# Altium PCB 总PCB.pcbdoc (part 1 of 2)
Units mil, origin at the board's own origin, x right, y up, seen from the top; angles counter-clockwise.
Board outline 1771.65 x 3543.31 mil, 2 copper layers (Top Layer, Bottom Layer), stack 62.205 mil thick; 115 components, 80 nets, 419 pads, 214 vias.
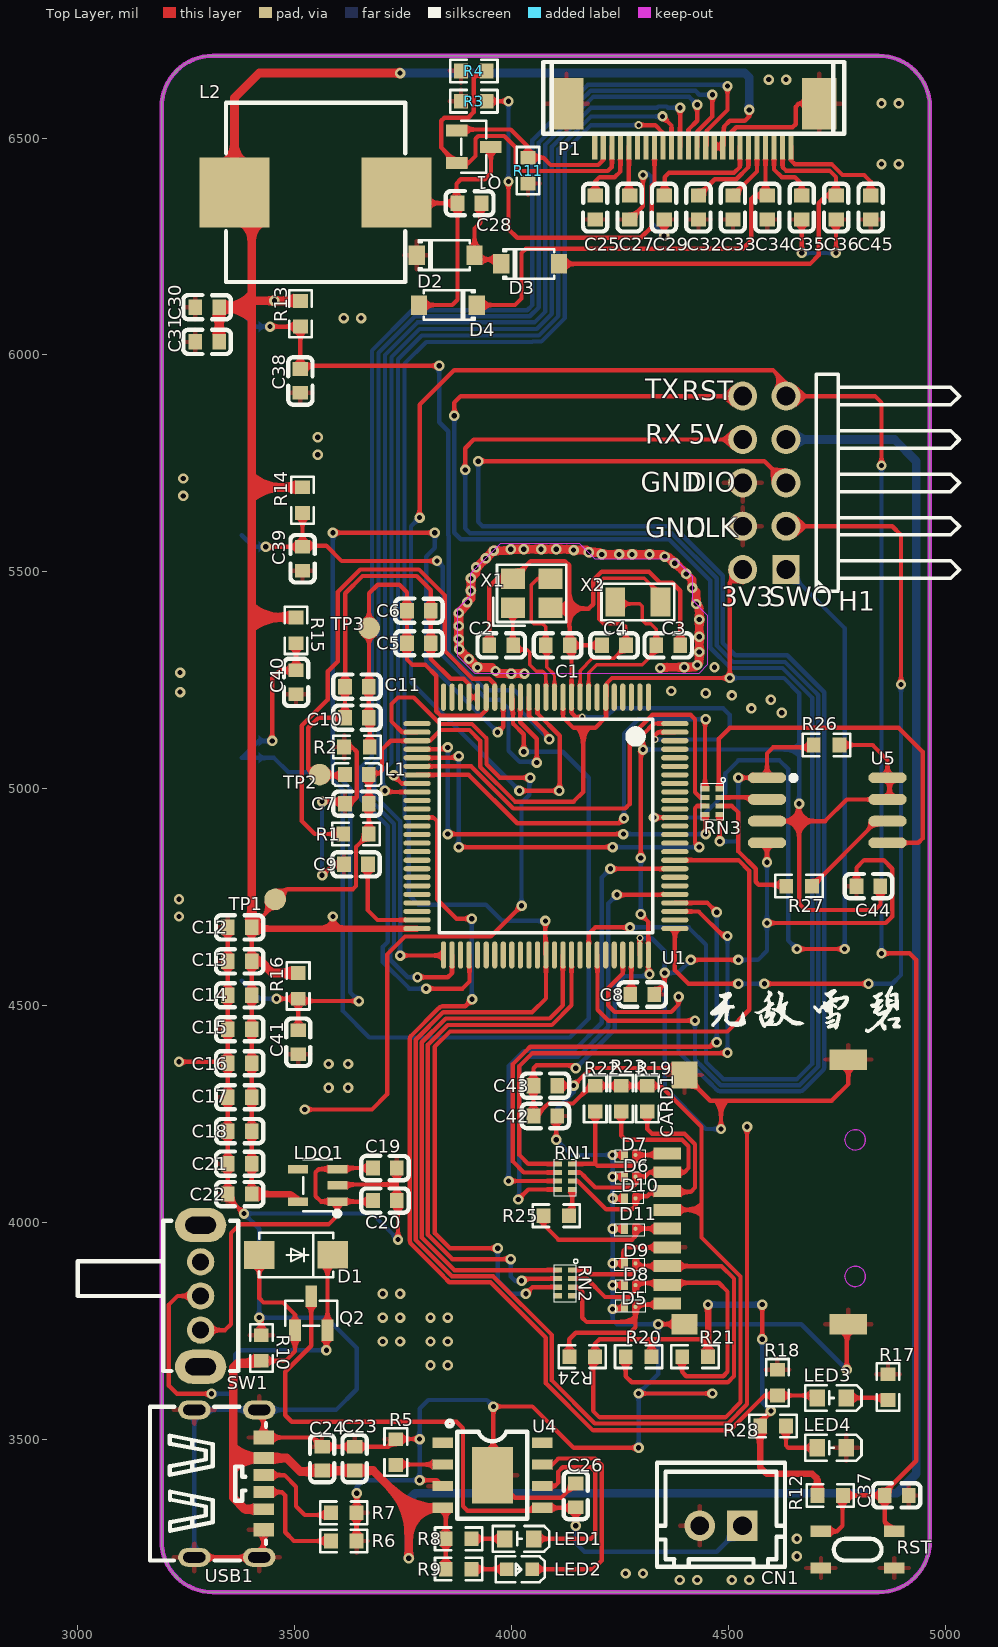
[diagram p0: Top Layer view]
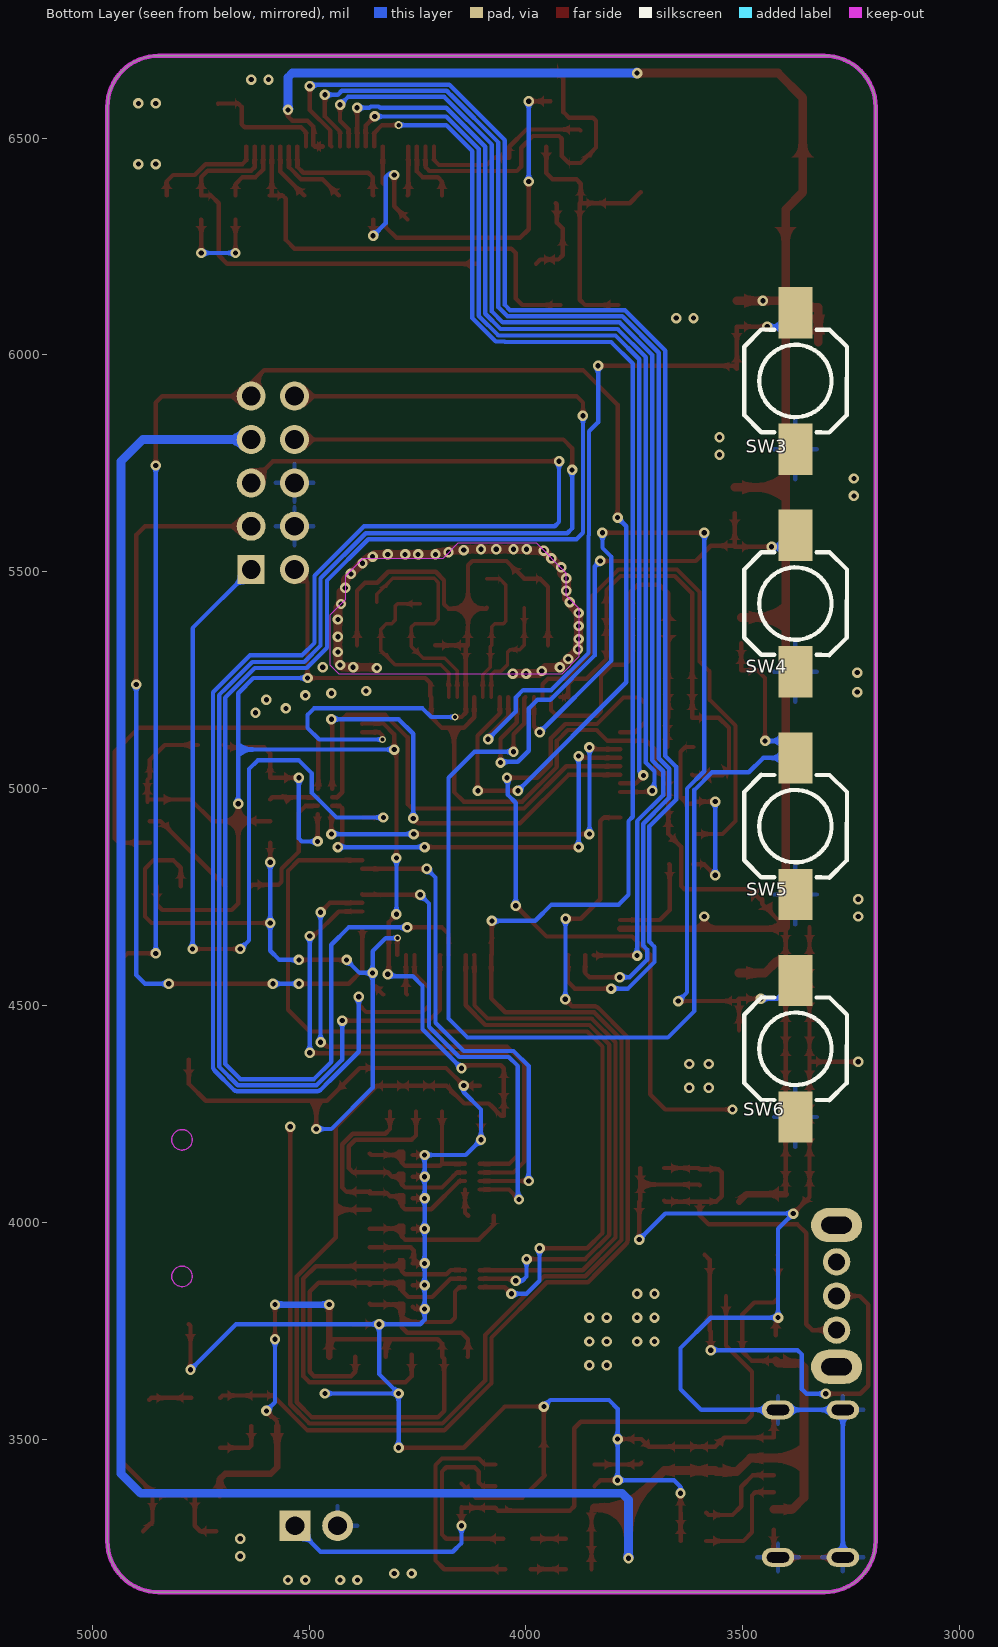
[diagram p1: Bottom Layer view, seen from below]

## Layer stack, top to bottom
Top Solder Mask Layer: solder mask 0.394, Dk 3.3
Top Layer: signal copper 1.378
Dielectric1: surface 59.449, FR4, Dk 4.5
Bottom Layer: signal copper 1.378
Bottom Solder Mask Layer: solder mask 0.394, Dk 3.3

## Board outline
3311.58,6690 4847.01,6690 cw(c4847.01,6571.89) 4965.12,6571.89 4965.12,3264.8 cw(c4847.01,3264.8) 4847.01,3146.69 3311.58,3146.69 cw(c3311.58,3264.8) 3193.47,3264.8 3193.47,6571.89 cw(c3311.58,6571.89)

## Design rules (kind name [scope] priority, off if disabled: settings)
BoardOutlineClearance copperThickness1oz [All] p0: genericclearance=10 ignorepadtopadclearanceinfootprint=FALSE except(0: Arc-SplitContinuation Track-SplitContinuation SMDPad-SplitContinuation THPad-SplitContinuation Via-SplitContinuation Fill-SplitContinuation Poly-SplitContinuation Region-SplitContinuation Text-SplitContinuation)
BoardOutlineClearance copperThickness2oz [All] p0: genericclearance=10 ignorepadtopadclearanceinfootprint=FALSE except(0: Arc-SplitContinuation Track-SplitContinuation SMDPad-SplitContinuation THPad-SplitContinuation Via-SplitContinuation Fill-SplitContinuation Poly-SplitContinuation Region-SplitContinuation Text-SplitContinuation)
BoardOutlineClearance copperThicknessInner0.5oz [All] p0: genericclearance=10 ignorepadtopadclearanceinfootprint=FALSE except(0: Arc-SplitContinuation Track-SplitContinuation SMDPad-SplitContinuation THPad-SplitContinuation Via-SplitContinuation Fill-SplitContinuation Poly-SplitContinuation Region-SplitContinuation Text-SplitContinuation)
BoardOutlineClearance otherClearance [All] p0: genericclearance=10 ignorepadtopadclearanceinfootprint=FALSE except(0: Arc-SplitContinuation Track-SplitContinuation SMDPad-SplitContinuation THPad-SplitContinuation Via-SplitContinuation Fill-SplitContinuation Poly-SplitContinuation Region-SplitContinuation Text-SplitContinuation)
Clearance copperThickness1oz [All] p1: gap=7 ignorepadtopadclearanceinfootprint=FALSE
Clearance copperThickness2oz [All] p1: gap=7 ignorepadtopadclearanceinfootprint=FALSE
Clearance copperThicknessInner0.5oz [All] p1: gap=7 ignorepadtopadclearanceinfootprint=FALSE
Clearance otherClearance [All] p1: gap=7 ignorepadtopadclearanceinfootprint=FALSE
DiffPairsRouting differentialPair [All] p1: maxuncoupledlength=10 minlimit=5.9843 maxlimit=Infinity mostfreqgap=5.9843 toplayer_minwidth=5 toplayer_prefwidth=10 toplayer_maxwidth=100 bottomlayer_minwidth=5 bottomlayer_prefwidth=10 bottomlayer_maxwidth=100
PasteMaskExpansion pasteMaskExpansion [All] p1: expansion=0
PlaneConnect innerPlane [All] p1: planeconnectstyle=Relief reliefexpansion=20 reliefentries=4 reliefconductorwidth=10 reliefairgap=10
PolygonConnect copperRegion [All] p1: connectstyle=Relief reliefentries=4 reliefconductorwidth=10 polygonreliefangle="90 Angle" airgapwidth=10
RoutingVias viaSize [All] p1: viastyle="Through Hole" holewidth=12.0078 minholewidth=7.874 maxholewidth=248.0314 width=12.0078 minwidth=7.874 maxwidth=248.0314
SolderMaskExpansion solderMaskExpansion [IsVia] p1: useseparateexpansions=TRUE expansion=-1000 expansionbottom=-1000
SolderMaskExpansion solderMaskExpansion [All] p2: useseparateexpansions=TRUE expansion=2.0079 expansionbottom=2.0079
Width copperThickness1oz [All] p1: maxlimit=100 minlimit=4 preferedwidth=10
Width copperThickness2oz [All] p1: maxlimit=100 minlimit=8 preferedwidth=10
Width copperThickness0.5oz [All] p1: maxlimit=100 minlimit=4 preferedwidth=10

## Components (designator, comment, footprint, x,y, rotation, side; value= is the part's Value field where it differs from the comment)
C1 "20pF" C0603#1 4106.72,5330.21 r180 top
C2 "20pF" C0603#1 3976.72,5330.21 r0 top
C3 "12pF" C0603#1 4361.72,5330.21 r180 top
C4 "12pF" C0603#1 4236.72,5330.21 r0 top
C5 "1uF" C0603#1 3786.72,5335.21 r0 top
C6 "100nF" C0603#1 3786.72,5410.21 r180 top
C7 "100nF" C0603#1 3643.91,4965.21 r180 top
C8 "2.2uF" C0603#1 4301.72,4525.21 r180 top
C9 "2.2uF" C0603#1 3641.72,4825.21 r0 top
C10 "1uF" C0603#1 3643.91,5163.57 r0 top
C11 "100nF" C0603#1 3643.91,5235.21 r180 top
C12 "10uF" C0603#1 3373.47,4680 r0 top
C13 "100nF" C0603#1 3373.47,4601.67 r0 top
C14 "100nF" C0603#1 3373.47,4523.33 r0 top
C15 "100nF" C0603#1 3373.47,4445 r0 top
C16 "100nF" C0603#1 3373.47,4366.67 r0 top
C17 "100nF" C0603#1 3373.47,4288.33 r0 top
C18 "100nF" C0603#1 3373.47,4210 r0 top
C19 "100nF" C0603#1 3708.47,4125 r180 top
C20 "1uF" C0603#1 3708.47,4050 r180 top
C21 "1uF" C0603#1 3373.47,4135 r0 top
C22 "100nF" C0603#1 3373.47,4065 r0 top
C23 "22uF" C0603#1 3638.47,3455 r270 top
C24 "100nF" C0603#1 3563.47,3455 r90 top
C25 "100nF" C0603#2 4193.47,6340 r90 top
C26 "10uF" C0603#1 4148.47,3370 r270 top
C27 "100nF" C0603#2 4272.84,6340 r90 top
C28 "100nF" C0603#2 3903.47,6350 r180 top
C29 "100nF" C0603#2 4352.22,6340 r90 top
C30 "100nF" C0603#2 3298.47,6110 r0 top
C31 "100nF" C0603#2 3298.47,6030 r0 top
C32 "100nF" C0603#2 4431.59,6340 r90 top
C33 "100nF" C0603#2 4510.97,6340 r90 top
C34 "100nF" C0603#2 4590.34,6340 r90 top
C35 "100nF" C0603#2 4669.72,6340 r90 top
C36 "100nF" C0603#2 4749.09,6340 r90 top
C37 "100nF" C0603#1 4888.47,3370 r0 top
C38 "100nF" C0603#1 3513.47,5940 r90 top
C39 "100nF" C0603#1 3518.47,5530 r90 top
C40 "100nF" C0603#1 3503.47,5245 r90 top
C41 "100nF" C0603#1 3508.47,4415 r90 top
C42 "10uF" C0603#1 4078.47,4245 r0 top
C43 "100nF" C0603#1 4078.47,4315 r180 top
C44 "100nF" C0603#1 4823.47,4775 r180 top
C45 "100nF" C0603#2 4828.47,6340 r90 top
CARD1 "XKTF-015-G" TF-SMD_XKTF-015-N 4568.47,4070 r90 top
CN1 "ZX-XH2.54-2PZZ" CONN-TH_2P-P2.50_HX25003-2A 4483.47,3300 r180 top
D1 "SS34" SMA_L4.3-W2.6-LS5.0-FD 3503.47,3925 r0 top
D2 "B5819W" SOD-123_L2.8-W1.8-LS3.7-RD 3848.47,6230 r0 top
D3 "B5819W" SOD-123_L2.8-W1.8-LS3.7-RD 4043.47,6210 r0 top
D4 "B5819W" SOD-123_L2.8-W1.8-LS3.7-RD 3853.47,6115 r180 top
D5 "LESD8D5.0CAT5G" DFN-2L_L1.0-W0.6-P0.65-BI 4273.47,3805 r180 top
D6 "LESD8D5.0CAT5G" DFN-2L_L1.0-W0.6-P0.65-BI 4273.47,4105 r180 top
D7 "LESD8D5.0CAT5G" DFN-2L_L1.0-W0.6-P0.65-BI 4273.47,4155 r180 top
D8 "LESD8D5.0CAT5G" DFN-2L_L1.0-W0.6-P0.65-BI 4273.47,3855 r180 top
D9 "LESD8D5.0CAT5G" DFN-2L_L1.0-W0.6-P0.65-BI 4273.47,3905 r180 top
D10 "LESD8D5.0CAT5G" DFN-2L_L1.0-W0.6-P0.65-BI 4273.47,4055 r180 top
D11 "LESD8D5.0CAT5G" DFN-2L_L1.0-W0.6-P0.65-BI 4273.47,3985 r180 top
H1 "PH2.54-07-05PWS" HDR-TH_10P-P2.54-H-M-R2-C5-S2.54-W12.9 4583.47,5705 r90 top
L1 "GZ1608D601TF" L0603 3643.91,5032.49 r180 top
L2 "68uH" IND-SMD_L11.5-W10.5_SRG1040 3548.47,6375 r0 top
LDO1 "ME6211C33M5G-N" SOT-23-5_L3.0-W1.7-P0.95-LS2.8-BL 3553.47,4085 r90 top
LED1 "GL0603UR01" LED0603-FD 4018.47,3270 r0 top
LED2 "MHT192DUGCT" LED0603-RD 4018.47,3200 r180 top
LED3 "GL0603UR01" LED0603-FD 4738.47,3595 r0 top
LED4 "GL0603UR01" LED0603-FD 4738.47,3480 r0 top
P1 "AFC07-S24ECC-00" FPC-SMD_24P-L17.5-W5.4-P0.50 4418.47,6530 r180 top
Q1 "SI2300" SOT-23-3_L2.9-W1.3-P1.90-LS2.4-BR#1 3913.47,6480 r180 top
Q2 "DMP1045U-7" SOT-23-3_L2.9-W1.3-P1.90-LS2.4-BR#2 3538.47,3790 r270 top
R1 "0Ω" R0603 3641.72,4895.21 r180 top
R2 "0Ω" R0603 3643.91,5095.87 r0 top
R3 "10K" R0603 3913.47,6585 r0 top
R4 "10K" R0603 3913.47,6655 r180 top
R5 "1.2kΩ" R0603 3733.47,3470 r270 top
R6 "5.1kΩ" R0603 3613.47,3265 r0 top
R7 "5.1kΩ" R0603 3613.47,3330 r0 top
R8 "1kΩ" R0603 3878.47,3270 r0 top
R9 "1kΩ" R0603 3878.47,3200 r0 top
R10 "10kΩ" R0603 3423.47,3710 r90 top
R11 "10K" R0603 4038.47,6425 r90 top
R12 "10kΩ" R0603 4735.36,3370.1 r180 top
R13 "10K" R0603 3513.47,6095 r90 top
R14 "10K" R0603 3518.47,5665 r90 top
R15 "10K" R0603 3503.47,5365 r90 top
R16 "10K" R0603 3508.47,4545 r90 top
R17 "2kΩ" R0603 4868.47,3620 r90 top
R18 "10kΩ" R0603 4613.47,3630 r270 top
R19 "47kΩ" R0603 4313.47,4285 r90 top
R20 "47kΩ" R0603 4293.47,3690 r0 top
R21 "47kΩ" R0603 4423.47,3690 r0 top
R22 "47kΩ" R0603 4193.47,4285 r90 top
R23 "47kΩ" R0603 4253.47,4285 r90 top
R24 "47kΩ" R0603 4163.47,3690 r0 top
R25 "22Ω" R0603 4103.47,4015 r180 top
R26 "10kΩ" R0603 4726.89,5100.5 r0 top
R27 "22Ω" R0603 4663.47,4775 r180 top
R28 "2kΩ" R0603 4603.47,3530 r0 top
RN1 "0Ω" RES-ARRAY-SMD_0402-8P-L2.0-W1.0-BL 4123.47,4105 r270 top
RN2 "0Ω" RES-ARRAY-SMD_0402-8P-L2.0-W1.0-BL 4123.47,3860 r270 top
RN3 "0Ω" RES-ARRAY-SMD_0402-8P-L2.0-W1.0-BL 4463.47,4970 r270 top
RST "TSA017A2540A03" SW-SMD_4P-L4.2-W3.4-P2.15-LS5.2 4798.47,3245 r180 top
SW1 "SK12D07VG5" SW-TH_SK12D07VG5-1 3283.47,3830 r270 top
SW3 "TS-1817A-5026" SW-SMD_L6.0-W6.0-LS8.0 3378.47,5940 r90 bottom
SW4 "TS-1817A-5026" SW-SMD_L6.0-W6.0-LS8.0 3378.47,5426.67 r90 bottom
SW5 "TS-1817A-5026" SW-SMD_L6.0-W6.0-LS8.0 3378.47,4913.33 r90 bottom
SW6 "TS-1817A-5026" SW-SMD_L6.0-W6.0-LS8.0 3378.47,4400 r90 bottom
TP1 "" Test-Point-0.5mm 3455.17,4744.65 r0 top
TP2 "" Test-Point-0.5mm 3558.12,5032.28 r0 top
TP3 "" Test-Point-0.5mm 3671.72,5370.21 r0 top
U1 "" LQFP-100_L14.0-W14.0-P0.50-LS16.0-BL 4079.75,4913.56 r180 top locked
U4 "TC4056A." ESOP-8_L4.9-W3.9-P1.27-LS6.0-BL-EP 3956.19,3416.49 r270 top
U5 "GD25Q32CSIGR" SOIC-8_L5.3-W5.3-P1.27-LS8.0-BL 4728.47,4950 r270 top
USB1 "TYPE-C 6P" TYPE-C-SMD_TYPE-C-6P_1 3348.73,3397.2 r270 top
X1 "8MHz" CRYSTAL-SMD_4P-L3.2-W2.5-BL 4046.72,5450.21 r0 top
X2 "32.768kHz" OSC-SMD_2P-L3.2-W1.5 4291.72,5430.21 r0 top

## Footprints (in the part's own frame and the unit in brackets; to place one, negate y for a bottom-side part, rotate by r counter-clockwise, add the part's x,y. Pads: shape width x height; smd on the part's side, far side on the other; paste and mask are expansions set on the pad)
C0603#1 [mm]
  rect 0.8x0.9 smd: 1(-0.7,0) 2(0.7,0)
  silkscreen extent -1.39,-0.71 1.39,0.71
C0603#2 [mm]
  rect 0.8x0.9 smd paste+0 mask+0.051: 1(-0.7,0) 2(0.7,0)
  silkscreen extent -1.41,-0.71 1.39,0.72
CONN-TH_2P-P2.50_HX25003-2A [mm]
  rect 1.8x1.8 hole 1.1 paste+0 mask+0.05: 1(-1.25,0)
  round 1.8 hole 1.1 paste+0 mask+0.05: 2(1.25,0)
  silkscreen extent -3.75,-3.7 3.75,2.41
CRYSTAL-SMD_4P-L3.2-W2.5-BL [mm]
  rect 1.4x1.2 smd: 1(-1.1,-0.85) 2(1.1,-0.85) 3(1.1,0.85) 4(-1.1,0.85)
  silkscreen extent -2.26,-1.91 2.03,1.68
DFN-2L_L1.0-W0.6-P0.65-BI [mm]
  round 0.246 smd: 1(-0.325,0)
  rect 0.4x0.6 smd: 2(0.325,0)
  Top Layer region: -0.53,0.3 -0.53,-0.3 -0.2,-0.3 -0.12,-0.2 -0.12,0.3
ESOP-8_L4.9-W3.9-P1.27-LS6.0-BL-EP [mm]
  rect 0.6x1.2 smd: 1(-1.905,-2.908) 2(-0.635,-2.908) 3(0.635,-2.908) 4(1.905,-2.908) 5(1.905,2.908) 6(0.635,2.908) 7(-0.635,2.908) 8(-1.905,2.908)
  rect 3.3x2.4 smd: 9(0,0)
  silkscreen extent -3.2,-2.67 2.55,2.05
FPC-SMD_24P-L17.5-W5.4-P0.50 [mm]
  rect 0.3x1.5 smd: 1(5.745,1.25) 2(5.245,1.25) 3(4.746,1.25) 4(4.245,1.25) 5(3.746,1.25) 6(3.245,1.25) 7(2.746,1.25) 8(2.245,1.25) 9(1.746,1.25) 10(1.245,1.25) 11(0.746,1.25) 12(0.245,1.25) 13(-0.254,1.25) 14(-0.755,1.25) 15(-1.251,1.25) 16(-1.754,1.25) 17(-2.254,1.25) 18(-2.754,1.25) 19(-3.254,1.25) 20(-3.756,1.25) 21(-4.256,1.25) 22(-4.756,1.25) 23(-5.256,1.25) 24(-5.757,1.25)
  rect 2x3 smd: 25(-7.401,-1.25) 26(7.401,-1.25)
  silkscreen extent -8.87,-3.7 8.77,0.5
HDR-TH_10P-P2.54-H-M-R2-C5-S2.54-W12.9 [mm]
  rect 1.7x1.575 hole 1.1: 1(-5.08,-1.27)
  round 1.7 hole 1.1: 2(-5.08,1.27) 3(-2.54,-1.27) 4(-2.54,1.27) 5(0,-1.27) 6(0,1.27) 7(2.54,-1.27) 8(2.54,1.27) 9(5.08,-1.27) 10(5.08,1.27)
  silkscreen extent -6.35,-11.43 6.35,-3.05
IND-SMD_L11.5-W10.5_SRG1040 [mm]
  rect 4.1x4.1 smd: 1(-4.75,0) 2(4.75,0)
  silkscreen extent -5.25,-5.25 5.25,5.25
L0603 [mm]
  rect 0.8x0.864 smd paste-100 mask+0.051: 1(-0.7,0) 2(0.7,0)
  silkscreen extent -1.42,-0.65 1.42,0.65
LED0603-FD [mm]
  rect 0.9x1 smd: 1(-0.85,0) 2(0.85,0)
  silkscreen extent -1.55,-0.75 1.75,0.75
LED0603-RD [mm]
  rect 0.8x0.8 smd: 1(-0.749,0) 2(0.749,0)
  silkscreen extent -1.49,-0.75 1.39,0.76
LQFP-100_L14.0-W14.0-P0.50-LS16.0-BL [mm]
  oval 0.3x1.6 smd paste-100 mask+0.051: 1(-6,-7.55) 2(-5.5,-7.55) 3(-5,-7.55) 4(-4.5,-7.55) 5(-4,-7.55) 6(-3.5,-7.55) 7(-3,-7.55) 8(-2.5,-7.55) 9(-2,-7.55) 10(-1.5,-7.55) 11(-1,-7.55) 12(-0.5,-7.55) 13(0,-7.55) 14(0.5,-7.55) 15(1,-7.55) 16(1.5,-7.55) 17(2,-7.55) 18(2.5,-7.55) 19(3,-7.55) 20(3.5,-7.55) 21(4,-7.55) 22(4.5,-7.55) 23(5,-7.55) 24(5.5,-7.55) 25(6,-7.55) 51(6,7.55) 52(5.5,7.55) 53(5,7.55) 54(4.5,7.55) 55(4,7.55) 56(3.5,7.55) 57(3,7.55) 58(2.5,7.55) 59(2,7.55) 60(1.5,7.55) 61(1,7.55) 62(0.5,7.55) 63(0,7.55) 64(-0.5,7.55) 65(-1,7.55) 66(-1.5,7.55) 67(-2,7.55) 68(-2.5,7.55) 69(-3,7.55) 70(-3.5,7.55) 71(-4,7.55) 72(-4.5,7.55) 73(-5,7.55) 74(-5.5,7.55) 75(-6,7.55)
  oval 1.6x0.3 smd paste-100 mask+0.051: 26(7.55,-6) 27(7.55,-5.5) 28(7.55,-5) 29(7.55,-4.5) 30(7.55,-4) 31(7.55,-3.5) 32(7.55,-3) 33(7.55,-2.5) 34(7.55,-2) 35(7.55,-1.5) 36(7.55,-1) 37(7.55,-0.5) 38(7.55,0) 39(7.55,0.5) 40(7.55,1) 41(7.55,1.5) 42(7.55,2) 43(7.55,2.5) 44(7.55,3) 45(7.55,3.5) 46(7.55,4) 47(7.55,4.5) 48(7.55,5) 49(7.55,5.5) 50(7.55,6) 76(-7.55,6) 77(-7.55,5.5) 78(-7.55,5) 79(-7.55,4.5) 80(-7.55,4) 81(-7.55,3.5) 82(-7.55,3) 83(-7.55,2.5) 84(-7.55,2) 85(-7.55,1.5) 86(-7.55,1) 87(-7.55,0.5) 88(-7.55,0) 89(-7.55,-0.5) 90(-7.55,-1) 91(-7.55,-1.5) 92(-7.55,-2) 93(-7.55,-2.5) 94(-7.55,-3) 95(-7.55,-3.5) 96(-7.55,-4) 97(-7.55,-4.5) 98(-7.55,-5) 99(-7.55,-5.5) 100(-7.55,-6)
  silkscreen extent -6.25,-6.25 6.25,6.25
OSC-SMD_2P-L3.2-W1.5 [mm]
  rect 1.15x1.7 smd: 1(-1.325,0) 2(1.325,0)
  silkscreen extent -2.39,-1.08 2.13,1.37
R0603 [mil]
  rect 31.75x34.02 smd paste-3937.01 mask+2: 1(-29.66,0) 2(29.66,0)
  silkscreen extent -55,-26 55,26
RES-ARRAY-SMD_0402-8P-L2.0-W1.0-BL [mm]
  rect 0.3x0.505 smd: 1(-0.75,0.427) 2(-0.25,0.427) 3(0.25,0.427) 4(0.75,0.427) 5(0.75,-0.427) 6(0.25,-0.427) 7(-0.25,-0.427) 8(-0.75,-0.427)
  silkscreen extent -1.31,0.59 -1.08,0.83
SMA_L4.3-W2.6-LS5.0-FD [mm]
  rect 1.8x1.62 smd: 1(-2.15,-0.009) 2(2.15,0.009)
  silkscreen extent -2.17,-1.32 2.19,1.29
SOD-123_L2.8-W1.8-LS3.7-RD [mm]
  rect 0.95x1.15 smd paste+0 mask+0.051: 1(-1.692,0) 2(1.692,0)
  silkscreen extent -1.58,-0.87 1.41,0.87
SOIC-8_L5.3-W5.3-P1.27-LS8.0-BL [mm]
  oval 0.63x2.25 smd: 1(-1.905,-3.53) 2(-0.635,-3.53) 3(0.635,-3.53) 4(1.905,-3.53) 5(1.905,3.53) 6(0.635,3.53) 7(-0.635,3.53) 8(-1.905,3.53)
  silkscreen extent -2.04,-2.13 -1.74,-1.83
SOT-23-3_L2.9-W1.3-P1.90-LS2.4-BR#1 [mm]
  rect 1.25x0.7 smd paste+0 mask+0.051: 1(1,-0.95) 2(1,0.95) 3(-1,0)
  silkscreen extent -0.73,-1.53 0.73,1.53
SOT-23-3_L2.9-W1.3-P1.90-LS2.4-BR#2 [mm]
  rect 1.25x0.7 smd: 1(1,-0.95) 2(1,0.95) 3(-1,0)
  silkscreen extent -0.73,-1.53 0.73,1.53
SOT-23-5_L3.0-W1.7-P0.95-LS2.8-BL [mm]
  rect 0.49x1.157 smd: 1(-0.95,-1.154) 2(0,-1.154) 3(0.95,-1.154)
  rect 0.49x1.175 smd: 4(0.95,1.154) 5(-0.95,1.154)
  silkscreen extent -1.8,-1.29 1.53,0.85
SW-SMD_4P-L4.2-W3.4-P2.15-LS5.2 [mm]
  rect 1.2x0.65 smd: 1(-2.15,1.075) 2(2.15,1.075) 3(-2.15,-1.075) 4(2.15,-1.075)
  silkscreen extent -1.4,-0.63 1.39,0.64
SW-SMD_L6.0-W6.0-LS8.0 [mm]
  rect 3x2 smd: 1(-4,0) 2(4,0)
  silkscreen extent -3.02,-3.02 3.01,3
SW-TH_SK12D07VG5-1 [mm]
  round 1.6 hole 1: 1(-2,0) 2(0,0) 3(2,0)
  oval 2x3 hole 1 slot 1.8 at 90 deg: 4(4.15,0) 5(-4.15,0)
  silkscreen extent -4.4,-7.2 4.4,2.2
Test-Point-0.5mm [mil]
  round 50 smd: 1(0,0)
TF-SMD_XKTF-015-N [mm]
  rect 0.7x1.6 smd: 1(2.25,5.3) 2(1.15,5.3) 3(0.05,5.3) 4(-1.05,5.3) 5(-2.15,5.3) 6(-3.25,5.3) 7(-4.35,5.3) 8(-5.45,5.3) 9(-6.55,5.3)
  rect 1.2x1.5 smd: 10(-7.75,4.3)
  rect 1.2x2.2 smd: 11(-7.75,-5.3) 13(7.75,-5.3)
  rect 1.6x1.5 smd: 12(6.85,4.3)
  Board Outline Layer circle w0.003: c3.05,-5.7 r0.6
  Board Outline Layer circle w0.003: c-4.95,-5.7 r0.6
  Board Outline Layer region: 3.05,-6.3 2.79,-6.241 2.581,-6.074 2.465,-5.834 2.465,-5.567 2.581,-5.326 2.79,-5.159 3.05,-5.1 3.05,-5.1 3.31,-5.159 3.519,-5.326 3.635,-5.567 3.635,-5.834 3.519,-6.074 3.31,-6.241 3.05,-6.3
  Board Outline Layer region: 3.05,-6.3 2.79,-6.241 2.581,-6.074 2.465,-5.834 2.465,-5.567 2.581,-5.326 2.79,-5.159 3.05,-5.1 3.05,-5.1 3.31,-5.159 3.519,-5.326 3.635,-5.567 3.635,-5.834 3.519,-6.074 3.31,-6.241 3.05,-6.3
  Board Outline Layer region: -4.95,-6.3 -5.21,-6.241 -5.419,-6.074 -5.535,-5.834 -5.535,-5.567 -5.419,-5.326 -5.21,-5.159 -4.95,-5.1 -4.95,-5.1 -4.69,-5.159 -4.481,-5.326 -4.365,-5.567 -4.365,-5.834 -4.481,-6.074 -4.69,-6.241 -4.95,-6.3
  Board Outline Layer region: -4.95,-6.3 -5.21,-6.241 -5.419,-6.074 -5.535,-5.834 -5.535,-5.567 -5.419,-5.326 -5.21,-5.159 -4.95,-5.1 -4.95,-5.1 -4.69,-5.159 -4.481,-5.326 -4.365,-5.567 -4.365,-5.834 -4.481,-6.074 -4.69,-6.241 -4.95,-6.3
TYPE-C-SMD_TYPE-C-6P_1 [mm]
  oval 1.1x1.9 hole 0.6 slot 1.3 at 90 deg: 7(-4.32,1.775) 7(-4.32,-2.025) 7(4.32,1.775) 7(4.32,-2.025)
  rect 0.7x1.2 smd paste-100 mask+0.051: A5(-0.5,2.025) A9(1.5,2.025) B5(0.5,2.025) B9(-1.5,2.025)
  rect 0.8x1.2 smd paste-100 mask+0.051: A12(2.7,2.025) B12(-2.7,2.025)
  silkscreen extent -4.5,-4.63 4.5,2.18

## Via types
v1: diameter 24.02, hole 12.01, Top Layer to Bottom Layer, 210 vias
v2: diameter 16, hole 9, Top Layer to Bottom Layer, 3 vias
v3: diameter 18, hole 10, Top Layer to Bottom Layer, 1 vias

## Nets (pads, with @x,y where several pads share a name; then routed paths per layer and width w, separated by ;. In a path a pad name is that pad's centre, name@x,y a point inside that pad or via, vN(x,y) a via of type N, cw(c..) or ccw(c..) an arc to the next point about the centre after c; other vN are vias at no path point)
$1I7\$2N9: C9.2 U1.49 | length 229.1
  Top Layer w10: C9.2@3669.28,4825.21 3668.47,4824.41 3668.47,4720 3691.45,4697.02 U1.49@3782.51,4697.02
$1I7\$2N12: R1.2 U1.19 | length 1268.2
  Top Layer w10: R1.2@3612.06,4895.21 3546.72,4895.21 3516.72,4925.21 3516.72,5145.21 3576.72,5205.21 3576.72,5270.21 3599.7,5293.2 3599.7,5453.2 3651.72,5505.21 3786.72,5505.21 3846.72,5445.21 3846.72,5316.99 3910.43,5253.28 3948.94,5253.28 3961.72,5240.51 3961.72,5210.88 U1.19@3961.64,5210.8
$1I7\$2N16: C8.2 U1.73 | length 92.1
  Top Layer w10: C8.2@4274.16,4525.21 4276.6,4527.66 U1.73@4276.6,4616.32
$1I7\BOOT0: U1.94
$1I7\OSC32_IN: C3.2 U1.8 X2.1 | length 416.2
  Top Layer w8: U1.8@4178.18,5210.8 4178.18,5266.68 4196.72,5285.21 4301.72,5285.21 4334.16,5317.65 C3.2@4334.16,5330.21 4334.16,5367.77 4321.72,5380.21 4309.72,5380.21 4301.72,5388.21 4301.72,5420.21 4296.06,5425.87 X2.1@4243.89,5425.87
$1I7\OSC32_OUT: C4.2 U1.9 X2.2 | length 569.3
  Top Layer w8: U1.9@4158.49,5210.8 4158.49,5271.99 4186.72,5300.21 4236.72,5300.21 4264.28,5327.77 C4.2@4264.28,5330.21 4264.28,5372.65 4256.72,5380.21 4211.72,5380.21 4201.72,5390.21 4201.72,5475.21 4211.72,5485.21 4306.72,5485.21 4343.89,5448.04 X2.2@4343.89,5430.21
$1I7\OSC_IN: C1.2 U1.12 X1.3 | length 342.4
  Top Layer w8: X1.3@4090.03,5483.68 4060.18,5483.68 4046.06,5469.56 4046.06,5385.87 4051.72,5380.21 4071.72,5380.21 4079.16,5372.77 C1.2@4079.16,5330.21 4081.72,5327.65 4081.72,5280.21 4099.43,5262.5 U1.12@4099.43,5210.8
$1I7\OSC_OUT: C2.2 U1.13 X1.1 | length 259.1
  Top Layer w8: X1.1@4003.41,5416.75 4003.41,5331.08 C2.2@4004.28,5330.21 4014.28,5320.21 4036.72,5320.21 4042.37,5314.56 4042.37,5285.21 4057.37,5270.21 4071.72,5270.21 4079.75,5262.18 U1.13@4079.75,5210.8
$1I7\PA9: H1.10 U1.68 | length 3777.1
  Top Layer w10: v1(3868.47,5860) 3868.47,5890 3883.47,5905 H1.10@4533.47,5905 ; U1.68@4178.18,4616.32 4178.47,4616.61 4178.47,4665 4193.47,4680 v1(4273.47,4680)
  Bottom Layer w10: v1(3868.47,5860) 3868.47,5590 3883.47,5575 4363.47,5575 4458.47,5480 4458.47,5325 4505.48,5277.99 4625.3,5277.99 4693.47,5209.82 4693.47,4365 4658.47,4330 4488.47,4330 4448.76,4369.71 4448.76,4640 4408.76,4680 v1(4273.47,4680)
$1I7\PA10: H1.8 U1.69 | length 3532.3
  Top Layer w10: v1(3893.47,5735) 3893.47,5785 3913.47,5805 H1.8@4533.47,5805 ; U1.69@4197.86,4616.32 4198.47,4615.71 4198.47,4490 4223.47,4465 v1(4423.47,4465)
  Bottom Layer w10: v1(3893.47,5735) 3893.47,5600 3904.45,5589.02 4369.45,5589.02 4473.47,5485 4473.47,5329.82 4511.28,5292.01 4631.1,5292.01 4698.11,5225 4698.47,5225 4705.54,5217.93 4705.54,5217.57 4707.48,5215.63 4707.48,4359.19 4664.27,4315.98 4482.66,4315.98 4443.65,4355 4443.47,4355 4423.47,4375 v1(4423.47,4465)
$1I7\SWCLK: H1.3 U1.76 | length 1926.9
  Top Layer w10: U1.76@4376.99,4677.34 4376.99,4581.48 4408.47,4550 v1(4523.47,4550) ; v1(4583.47,4550) v1(4823.47,4550) ; H1.3@4633.47,5605 4878.47,5605 4898.47,5585 v1(4898.47,5240)
  Bottom Layer w10: v1(4523.47,4550) v1(4583.47,4550) ; v1(4823.47,4550) 4878.47,4550 4898.47,4570 v1(4898.47,5240)
$1I7\SWDIO: H1.5 U1.72 | length 3634.6
  Top Layer w10: v1(3923.47,5755) 4583.47,5755 H1.5@4633.47,5705 ; U1.72@4256.92,4616.32 4256.92,4573.45 4223.47,4540 4223.47,4500 4238.47,4485 4368.47,4485 4385.54,4502.07 v1(4385.54,4520)
  Bottom Layer w10: v1(3923.47,5755) 3923.47,5615 3933.47,5605 4373.47,5605 4487.48,5490.98 4487.48,5335.98 4516.21,5307.26 4636.21,5307.26 4721.5,5221.97 4721.5,4359.19 cw(c4707.48,4359.19) 4717.39,4349.28 4674.18,4306.07 cw(c4664.27,4315.98) 4664.27,4301.97 4482.66,4301.97 cw(c4482.66,4315.98) 4472.75,4306.07 4453.83,4325 4453.47,4325 4385.54,4392.93 v1(4385.54,4520)
$1I7\SWO: H1.1 U1.89 | length 1906.9
  Top Layer w10: v1(4328.47,4933.24) U1.89@4376.99,4933.24 ; v1(4658.47,4630) v1@4763.47,4630
  Bottom Layer w10: v1(4328.47,4933.24) 4436.71,4933.24 4493.47,4990 4493.47,5035 4523.47,5065 4618.47,5065 4638.47,5045 4638.47,4650 v1(4658.47,4630) ; H1.1@4633.47,5505 4768.47,5370 v1(4768.47,4630)
$1I7\VDDA: C5.2 C6.1 C10.1 C11.2 L1.2 TP2.1 U1.21 U1.22 | length 1116.1
  Top Layer w8: U1.22@3902.58,5210.8 U1.21@3922.27,5210.8
  Top Layer w10: L1.2@3616.36,5032.49 3614.08,5030.21 3546.72,5030.21 3531.72,5045.21 3531.72,5140.21 3555.07,5163.57 C10.1@3616.35,5163.57 C11.2@3616.35,5235.21 3616.72,5235.58 3616.72,5450.21 3656.72,5490.21 3781.72,5490.21 3814.28,5457.65 C6.1@3814.28,5410.21 C5.2@3814.28,5335.21 3814.28,5299.1 3860.1,5253.28 3889.89,5253.28 3902.58,5240.6 U1.22@3902.58,5210.8
$1I10\$1N26: R27.1 U5.6 | length 236.5
  Top Layer w10: R27.1@4693.13,4775 4843.13,4925 U5.6@4867.45,4925
$1I10\$1N34: CARD1.5 D11.1 R25.2 | length 341.3
  Top Layer w10: R25.2@4073.81,4015 4073.81,3994.66 4108.47,3960 4278.47,3960 4286.26,3967.8 D11.1@4286.26,3985 4286.61,3985.35 CARD1.5@4359.81,3985.35
$1I10\_SD_CARD_DET: CARD1.9 D5.1 R24.1 RN2.3 | length 545.7
  Top Layer w10: R24.1@4133.81,3690 4133.47,3690.34 4133.47,3730 4148.47,3745 4273.47,3745 4286.26,3757.8 4286.26,3766.1 ; RN2.3@4140.3,3850.16 4153.31,3850.16 4163.47,3840 4163.47,3780 4173.47,3770 4282.37,3770 4286.26,3766.1 ; CARD1.9@4359.81,3812.12 4357.69,3810 4288.47,3810 4288.47,3807.2 D5.1@4286.26,3805 4286.26,3766.1
$1I10\_SDIO_CLK: R25.1 RN1.4 | length 63.4
  Top Layer w10: R25.1@4133.13,4015 4140.3,4022.17 RN1.4@4140.3,4075.47
$1I10\_SDIO_CMD: CARD1.3 D10.1 R19.1 RN1.3 | length 605.2
  Top Layer w10: RN1.3@4140.3,4095.16 4153.31,4095.16 4218.47,4030 4278.47,4030 4286.26,4037.8 D10.1@4286.26,4055 4291.26,4060 4313.47,4060 4320.44,4066.97 CARD1.3@4359.81,4066.97 ; R19.1@4313.47,4255.34 4313.47,4215 4324.45,4204.02 4399.27,4204.02 4423.47,4179.82 4423.47,4080 4413.47,4070 4361.78,4070 CARD1.3@4359.81,4071.97
$1I10\_SDIO_D0: CARD1.7 D9.1 R20.1 RN2.1 | length 942.8
  Top Layer w10: RN2.1@4140.3,3889.53 4140.77,3890 4173.29,3890 4183.29,3880 4278.47,3880 4286.26,3887.8 D9.1@4286.26,3905 ; R20.1@4263.81,3695 4263.47,3694.66 4263.47,3645 4277.48,3630.98 4499.27,3630.98 4513.47,3645.18 4513.47,3870 4484.73,3898.74 CARD1.7@4359.81,3898.74 4290,3898.74
$1I10\_SDIO_D1: CARD1.8 D8.1 R21.1 RN2.2 | length 738
  Top Layer w10: RN2.2@4140.3,3869.84 4173.63,3869.84 4215.97,3827.5 4247.95,3827.5 4248.25,3827.79 4271.26,3827.79 4286.26,3842.8 D8.1@4286.26,3855 ; 4286.26,3860 4355.24,3860 CARD1.8@4359.81,3855.43 ; CARD1.8@4359.81,3860.43 4478.04,3860.43 4498.47,3840 4498.47,3655 4488.47,3645 4403.47,3645 4393.47,3655 4393.47,3689.66 R21.1@4393.81,3690
$1I10\_SDIO_D2: CARD1.1 D7.1 R22.1 RN1.1 | length 364.3
  Top Layer w10: RN1.1@4140.3,4134.53 4193.94,4134.53 ; R22.1@4193.47,4255.34 4193.47,4135 4193.94,4134.53 ; CARD1.1@4359.81,4158.58 4356.23,4155 D7.1@4286.26,4155 4286.26,4137.8 4278.47,4130 4198.47,4130 4193.94,4134.53
$1I10\_SDIO_D3: CARD1.2 D6.1 R23.1 RN1.2 | length 582.6
  Top Layer w10: RN1.2@4140.3,4114.84 4159.16,4114.84 4169.29,4104.71 4169.29,4104.18 4193.47,4080 4278.47,4080 4286.26,4087.8 D6.1@4286.26,4105 4308.47,4105 4318.74,4115.27 CARD1.2@4359.81,4115.27 4360.08,4115 4398.47,4115 4408.47,4125 4408.47,4175 4393.47,4190 4263.47,4190 4253.47,4200 R23.1@4253.47,4255.34
$1I10\_SPI_CLK: R27.2 RN3.3 | length 300.5
  Top Layer w10: RN3.3@4480.3,4960.16 4508.31,4960.16 4523.47,4945 4523.47,4855 4563.47,4815 4563.47,4785 4570.54,4777.93 4630.88,4777.93 R27.2@4633.81,4775
$1I10\_SPI_CS: R26.1 RN3.4 U5.1 | length 486.1
  Top Layer w10: v1(4480.3,4878.17) RN3.4@4480.3,4940.47 ; v1(4523.47,5025) U5.1@4589.49,5025 4589.49,5081.02 4603.47,5095 4691.73,5095 R26.1@4697.23,5100.5
  Bottom Layer w10: v1(4480.3,4878.17) 4516.64,4878.17 4523.47,4885 v1(4523.47,5025)
$1I10\_SPI_MISO: RN3.2 U5.2 | length 111.2
  Top Layer w10: RN3.2@4480.3,4979.84 4584.65,4979.84 U5.2@4589.49,4975
$1I10\_SPI_MOSI: RN3.1 U5.5 | length 904.3
  Top Layer w10: RN3.1@4480.3,4999.53 4478.47,5001.36 4478.47,5115 4503.47,5140 4893.47,5140 4948.31,5085.16 4948.31,4885 4938.31,4875 U5.5@4867.45,4875
$1I10\SD_CARD_DET: RN2.6 U1.84 | length 2083.6
  Top Layer w10: v1(3968.47,3940) 3858.47,3940 3823.47,3975 3823.47,4405 3858.47,4440 4498.47,4440 4548.47,4490 4548.47,4810.18 4523.65,4835 4377.17,4835 U1.84@4376.99,4834.82 ; v1(4033.47,3835) 4048.63,3850.16 RN2.6@4106.64,3850.16
  Bottom Layer w10: v1(3968.47,3940) 3968.47,3865 3998.47,3835 v1(4033.47,3835)
$1I10\SDIO_CLK: RN1.5 U1.80 | length 1097.7
  Top Layer w10: v1(4015.97,4052.5) 4038.94,4075.47 RN1.5@4106.64,4075.47 ; v1(4243.47,4755) 4375.91,4755 U1.80@4376.99,4756.08
  Bottom Layer w10: v1(4015.97,4052.5) 4018.47,4055 4018.47,4360 4039.45,4380.98 4153.47,4380.98 4223.47,4450.98 4223.47,4735 v1(4243.47,4755)
$1I10\SDIO_CMD: RN1.6 U1.83 | length 1146.1
  Top Layer w10: v1(3993.63,4095.16) RN1.6@4106.64,4095.16 ; v1(4228.47,4815) 4376.86,4815 U1.83@4376.99,4815.13
  Bottom Layer w10: v1(3993.63,4095.16) 3993.63,4360.16 4028.47,4395 4143.47,4395 4208.47,4460 4208.47,4795 v1(4228.47,4815)
$1I10\SDIO_D0: RN2.8 U1.65 | length 1271.2
  Top Layer w10: RN2.8@4106.64,3889.53 3868.94,3889.53 3793.47,3965 3793.47,4415 3848.47,4470 4088.47,4470 4118.47,4500 4118.47,4615.67 U1.65@4119.12,4616.32
$1I10\SDIO_D1: RN2.7 U1.66 | length 1291.8
  Top Layer w10: v1(3998.47,3915) 3863.47,3915 3807.48,3970.98 3807.48,4409.19 3853.29,4455 4093.47,4455 4138.81,4500.34 U1.66@4138.81,4616.32 ; v1(4023.47,3865) 4028.31,3869.84 RN2.7@4106.64,3869.84
  Bottom Layer w10: v1(3998.47,3915) 3998.47,3875 4008.47,3865 v1(4023.47,3865)
$1I10\SDIO_D2: RN1.8 U1.78 | length 1208.6
  Top Layer w10: RN1.8@4106.64,4134.53 4038.94,4134.53 4018.47,4155 4018.47,4360 4048.47,4390 4497.69,4390 v1(4498.47,4390.78) ; U1.78@4376.99,4716.71 4431.76,4716.71 4488.47,4660 v1(4498.47,4660)
  Bottom Layer w10: v1(4498.47,4390.78) v1(4498.47,4660)
$1I10\SDIO_D3: RN1.7 U1.79 | length 1229.6
  Top Layer w10: RN1.7@4106.64,4114.84 4028.63,4114.84 4003.47,4140 4003.47,4365 4033.47,4395 4033.65,4395 4043.44,4404.79 4458.26,4404.79 v1@4468.47,4415 ; U1.79@4376.99,4736.39 4452.08,4736.39 v1(4473.47,4715)
  Bottom Layer w10: v1(4473.47,4415) v1(4473.47,4715)
$1I10\SPI_CLK: RN3.6 U1.30 | length 982.1
  Top Layer w10: U1.30@3782.51,5071.04 3874.51,5071.04 v1(3878.47,5075) ; v1(3878.47,4865) v1(4233.47,4865) ; v1(4433.47,4865) 4423.47,4875 4423.47,4955 4428.63,4960.16 RN3.6@4446.64,4960.16
  Bottom Layer w10: v1(3878.47,4865) v1(3878.47,5075) ; v1(4233.47,4865) v1(4433.47,4865)
$1I10\SPI_CS: RN3.5 U1.29 | length 914
  Top Layer w10: U1.29@3782.51,5090.73 3849.2,5090.73 v1(3853.47,5095) ; v1(3853.47,4895) v1(4258.47,4895) ; RN3.5@4446.64,4940.47 4448.47,4938.64 v1(4448.47,4895)
  Bottom Layer w10: v1(3853.47,4895) v1(3853.47,5095) ; v1(4258.47,4895) v1(4448.47,4895)
$1I10\SPI_MISO: RN3.7 U1.31 | length 1061.4
  Top Layer w10: U1.31@3782.51,5051.36 3907.11,5051.36 4004.23,4954.23 4262.7,4954.23 4272.7,4964.23 4272.7,5118.06 4324.64,5170 4413.47,5170 4423.47,5160 4423.47,4991.32 4434.95,4979.84 RN3.7@4446.64,4979.84
$1I10\SPI_MOSI: RN3.8 U1.32 | length 1087.1
  Top Layer w10: U1.32@3782.51,5031.67 3901.8,5031.67 4013.47,4920 4248.47,4920 v1(4259.71,4931.24) ; RN3.8@4446.64,4999.53 4446.64,5158.17 v1(4448.47,5160)
  Bottom Layer w10: v1(4259.71,4931.24) 4259.71,5126.24 4293.47,5160 v1(4448.47,5160)
$1I11\$1N8: LED3.2 R17.1 | length 98.5
  Top Layer w10: LED3.2@4771.93,3595 4863.81,3595 R17.1@4868.47,3590.34
$1I11\$1N37: LED4.1 R28.2 | length 118.7
  Top Layer w10: R28.2@4633.13,3530 4633.13,3485.34 4638.47,3480 LED4.1@4705,3480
